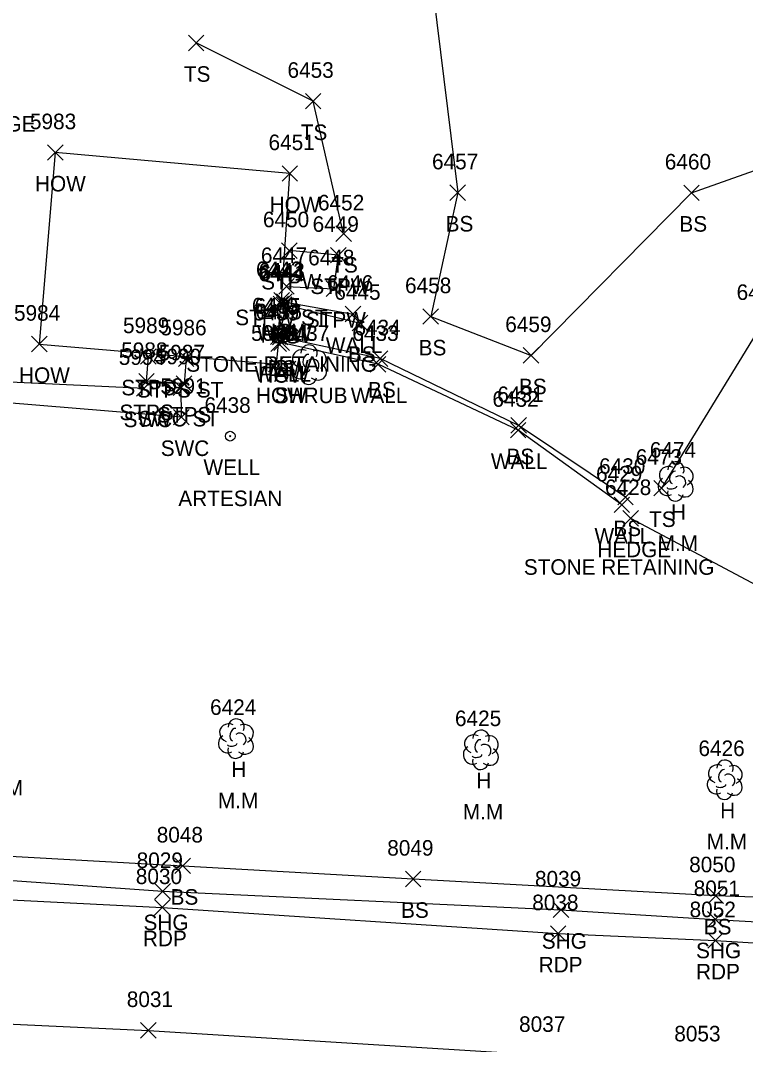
# Model space of a CAD drawing. Extents: x 1588028 to 1589597, y 137576 to 138176.
# Drawn here: x 1588574.1 to 1588667.4, y 137897.5 to 138029.2 of the extents above; entities that cross this region are included whole.
import ezdxf

# ---------------------------------------------------------------- set-up
doc = ezdxf.new("R2010")
doc.units = 0
for name, color, linetype in [('L_A', 7, 'Continuous'), ('L_C', 7, 'Continuous'), ('L_I', 7, 'Continuous'), ('L_TIC', 7, 'Continuous'), ('LAHR', 7, 'Continuous'), ('LBC', 7, 'Continuous'), ('LBF', 7, 'Continuous'), ('LELB', 7, 'Continuous'), ('LSH', 7, 'Continuous'), ('LTD', 7, 'Continuous'), ('LW', 7, 'Continuous'), ('P_A', 7, 'Continuous'), ('P_I', 7, 'Continuous'), ('P_TIC', 7, 'Continuous'), ('PET', 7, 'Continuous'), ('PRC', 7, 'Continuous'), ('PSU', 7, 'Continuous'), ('R_A', 7, 'Continuous'), ('R_I', 7, 'Continuous'), ('R_TIC', 7, 'Continuous'), ('RSW', 7, 'Continuous'), ('U_A', 7, 'Continuous'), ('U_C', 7, 'Continuous'), ('U_I', 7, 'Continuous'), ('UWW', 7, 'Continuous')]:
    doc.layers.add(name, color=color, linetype=linetype)

msp = doc.modelspace()

# ---------------------------------------------------------------- linework, layer by layer
at = {"layer": 'L_TIC'}
for points in [[(1588595.7, 138025.3), (1588597.7, 138027.3)], [(1588597.7, 138025.3), (1588595.7, 138027.3)], [(1588610.74, 138017.81), (1588612.74, 138019.81)], [(1588612.74, 138017.81), (1588610.74, 138019.81)], [(1588577.57, 138011.2), (1588579.57, 138013.2)], [(1588579.57, 138011.2), (1588577.57, 138013.2)], [(1588607.74, 138008.51), (1588609.74, 138010.51)], [(1588609.74, 138008.51), (1588607.74, 138010.51)], [(1588629.34, 138006.04), (1588631.34, 138008.04)], [(1588631.34, 138006.04), (1588629.34, 138008.04)], [(1588659.41, 138006.02), (1588661.41, 138008.02)], [(1588661.41, 138006.02), (1588659.41, 138008.02)], [(1588614.66, 138000.76), (1588616.66, 138002.76)], [(1588616.66, 138000.76), (1588614.66, 138002.76)], [(1588607.67, 137998.59), (1588609.67, 138000.59)], [(1588609.67, 137998.59), (1588607.67, 138000.59)], [(1588613.98, 137998), (1588615.98, 138000)], [(1588615.98, 137998), (1588613.98, 138000)], [(1588607.32, 137993.99), (1588609.32, 137995.99)], [(1588609.32, 137993.99), (1588607.32, 137995.99)], [(1588613.41, 137993.69), (1588615.41, 137995.69)], [(1588615.41, 137993.69), (1588613.41, 137995.69)], [(1588606.58, 137991.73), (1588608.58, 137993.73)], [(1588608.58, 137991.73), (1588606.58, 137993.73)], [(1588606.69, 137992.18), (1588608.69, 137994.18)], [(1588608.69, 137992.18), (1588606.69, 137994.18)], [(1588607, 137991.64), (1588609, 137993.64)], [(1588609, 137991.64), (1588607, 137993.64)], [(1588607.03, 137992.01), (1588609.03, 137994.01)], [(1588609.03, 137992.01), (1588607.03, 137994.01)], [(1588615.88, 137990.42), (1588617.88, 137992.42)], [(1588617.88, 137990.42), (1588615.88, 137992.42)], [(1588616.77, 137989.27), (1588618.77, 137991.27)], [(1588618.77, 137989.27), (1588616.77, 137991.27)], [(1588625.86, 137990.11), (1588627.86, 137992.11)], [(1588627.86, 137990.11), (1588625.86, 137992.11)], [(1588606.25, 137987.52), (1588608.25, 137989.52)], [(1588608.25, 137987.52), (1588606.25, 137989.52)], [(1588575.52, 137986.57), (1588577.52, 137988.57)], [(1588577.52, 137986.57), (1588575.52, 137988.57)], [(1588606.3, 137986.6), (1588608.3, 137988.6)], [(1588608.3, 137986.6), (1588606.3, 137988.6)], [(1588606.5, 137987.47), (1588608.5, 137989.47)], [(1588608.5, 137987.47), (1588606.5, 137989.47)], [(1588606.7, 137986.74), (1588608.7, 137988.74)], [(1588608.7, 137986.74), (1588606.7, 137988.74)], [(1588589.55, 137984.97), (1588591.55, 137986.97)], [(1588591.55, 137984.97), (1588589.55, 137986.97)], [(1588638.77, 137985.11), (1588640.77, 137987.11)], [(1588640.77, 137985.11), (1588638.77, 137987.11)], [(1588594.4, 137984.69), (1588596.4, 137986.69)], [(1588596.4, 137984.69), (1588594.4, 137986.69)], [(1588606.01, 137983.98), (1588608.01, 137985.98)], [(1588608.01, 137983.98), (1588606.01, 137985.98)], [(1588619.09, 137983.97), (1588621.09, 137985.97)], [(1588621.09, 137983.97), (1588619.09, 137985.97)], [(1588619.36, 137984.69), (1588621.36, 137986.69)], [(1588621.36, 137984.69), (1588619.36, 137986.69)], [(1588589.31, 137981.78), (1588591.31, 137983.78)], [(1588591.31, 137981.78), (1588589.31, 137983.78)], [(1588594.13, 137981.47), (1588596.13, 137983.47)], [(1588596.13, 137981.47), (1588594.13, 137983.47)], [(1588637.17, 137976.11), (1588639.17, 137978.11)], [(1588639.17, 137976.11), (1588637.17, 137978.11)], [(1588637.11, 137975.5), (1588639.11, 137977.5)], [(1588639.11, 137975.5), (1588637.11, 137977.5)], [(1588655.54, 137968.04), (1588657.54, 137970.04)], [(1588657.54, 137968.04), (1588655.54, 137970.04)], [(1588650.92, 137966.87), (1588652.92, 137968.87)], [(1588652.92, 137966.87), (1588650.92, 137968.87)], [(1588650.44, 137965.89), (1588652.44, 137967.89)], [(1588652.44, 137965.89), (1588650.44, 137967.89)], [(1588651.59, 137964.15), (1588653.59, 137966.15)], [(1588653.59, 137964.15), (1588651.59, 137966.15)], [(1588593.96, 137919.46), (1588595.96, 137921.46)], [(1588595.96, 137919.46), (1588593.96, 137921.46)], [(1588623.61, 137917.77), (1588625.61, 137919.77)], [(1588625.61, 137917.77), (1588623.61, 137919.77)], [(1588662.54, 137915.63), (1588664.54, 137917.63)], [(1588664.54, 137915.63), (1588662.54, 137917.63)]]:
    msp.add_lwpolyline(points, dxfattribs=at)
at = {"layer": 'LAHR'}
msp.add_lwpolyline([(1588676.23, 137952.57), (1588652.59, 137965.15)], dxfattribs=at)
at = {"layer": 'LBC'}
for points in [[(1588578.57, 138012.2), (1588576.52, 137987.57), (1588607.01, 137984.98), (1588607.3, 137987.6), (1588607.25, 137988.52), (1588607.58, 137992.73), (1588607.69, 137993.18), (1588608.74, 138009.51)], [(1588608.74, 138009.51), (1588578.57, 138012.2)]]:
    msp.add_lwpolyline(points, dxfattribs=at)
at = {"layer": 'LBF'}
for points in [[(1588608.32, 137994.99), (1588614.41, 137994.69), (1588614.98, 137999), (1588608.67, 137999.59)], [(1588595.4, 137985.69), (1588595.13, 137982.47), (1588590.31, 137982.78), (1588590.55, 137985.97)]]:
    msp.add_lwpolyline(points, dxfattribs=at)
at = {"layer": 'LELB'}
for points in [[(1588591.54, 138046.29), (1588626.32, 138039.75), (1588630.34, 138007.04), (1588626.86, 137991.11), (1588639.77, 137986.11), (1588660.41, 138007.02), (1588678.67, 138013.51), (1588710.59, 137997.46), (1588735.69, 137986.71)], [(1588615.66, 138001.76), (1588611.74, 138018.81), (1588596.7, 138026.3)], [(1588729.4, 137978.46), (1588684.34, 138002.79), (1588669.52, 137990.24), (1588656.54, 137969.04)], [(1588608, 137992.64), (1588617.77, 137990.27)], [(1588651.92, 137967.87), (1588638.17, 137977.11), (1588620.36, 137985.69), (1588607.5, 137988.47)], [(1588551.14, 137930.49), (1588555.16, 137922.7), (1588594.96, 137920.46), (1588624.61, 137918.77), (1588663.54, 137916.63), (1588704.8, 137915.23), (1588747.54, 137910.9), (1588783.34, 137911.62)]]:
    msp.add_lwpolyline(points, dxfattribs=at)
at = {"layer": 'LSH'}
msp.add_line((1588611.17, 137984.97), (1588611.17, 137984.97), dxfattribs=at)
msp.add_line((1588611.17, 137984.97), (1588611.17, 137984.97), dxfattribs=at)
msp.add_arc((1588611.22, 137986.41), 1.05, 335.5272, 180.9563, dxfattribs=at)
for centre, major_axis, ratio, start_param, end_param in [((1588610.38, 137985.64), (1.21, -0.51), 0.895232, 1.570796, 4.712389), ((1588612.21, 137985.56), (-1.14, -0.48), 0.949671, 1.570796, 4.712389), ((1588610.96, 137985.43), (-0.208, -0.792), 0.645439, 3.141593, 6.283185), ((1588611.67, 137984.81), (-0.5, 0.667), 0.989748, 3.141593, 6.283185), ((1588610.09, 137984.27), (0.58, -1.04), 0.959034, 3.141593, 6.283185), ((1588610.71, 137984.22), (-0.625, -0.083), 0.423636, 0, 3.141593), ((1588612.17, 137984.14), (-1.09, 0.79), 0.841452, 1.570796, 4.712389), ((1588611.17, 137983.47), (0.26, 1.06), 0.942809, 1.570796, 4.712389)]:
    msp.add_ellipse(centre, major_axis=major_axis, ratio=ratio, start_param=start_param, end_param=end_param, dxfattribs=at)
at = {"layer": 'LTD'}
for p, q in [((1588658.35, 137969.96), (1588658.35, 137969.96)), ((1588658.35, 137969.96), (1588658.35, 137969.96)), ((1588601.79, 137936.87), (1588601.79, 137936.87)), ((1588601.79, 137936.87), (1588601.79, 137936.87)), ((1588633.29, 137935.43), (1588633.29, 137935.43)), ((1588633.29, 137935.43), (1588633.29, 137935.43)), ((1588664.66, 137931.58), (1588664.66, 137931.58)), ((1588664.66, 137931.58), (1588664.66, 137931.58))]:
    msp.add_line(p, q, dxfattribs=at)
for centre in [(1588658.4, 137971.39), (1588601.84, 137938.3), (1588633.34, 137936.87), (1588664.71, 137933.02)]:
    msp.add_arc(centre, 1.05, 335.5272, 180.9563, dxfattribs=at)
for centre, major_axis, ratio, start_param, end_param in [((1588657.56, 137970.62), (1.21, -0.51), 0.895232, 1.570796, 4.712389), ((1588658.14, 137970.41), (-0.208, -0.792), 0.645439, 3.141593, 6.283185), ((1588659.39, 137970.54), (-1.14, -0.48), 0.949671, 1.570796, 4.712389), ((1588657.27, 137969.25), (0.58, -1.04), 0.959034, 3.141593, 6.283185), ((1588658.85, 137969.79), (-0.5, 0.667), 0.989748, 3.141593, 6.283185), ((1588659.35, 137969.12), (-1.09, 0.79), 0.841452, 1.570796, 4.712389), ((1588658.35, 137968.46), (0.26, 1.06), 0.942809, 1.570796, 4.712389), ((1588657.89, 137969.21), (-0.625, -0.083), 0.423636, 0, 3.141593), ((1588601, 137937.53), (1.21, -0.51), 0.895232, 1.570796, 4.712389), ((1588601.58, 137937.32), (-0.208, -0.792), 0.645439, 3.141593, 6.283185), ((1588602.83, 137937.45), (-1.14, -0.48), 0.949671, 1.570796, 4.712389), ((1588600.71, 137936.16), (0.58, -1.04), 0.959034, 3.141593, 6.283185), ((1588602.29, 137936.7), (-0.5, 0.667), 0.989748, 3.141593, 6.283185), ((1588602.79, 137936.03), (-1.09, 0.79), 0.841452, 1.570796, 4.712389), ((1588632.5, 137936.1), (1.21, -0.51), 0.895232, 1.570796, 4.712389), ((1588634.33, 137936.01), (-1.14, -0.48), 0.949671, 1.570796, 4.712389), ((1588601.79, 137935.37), (0.26, 1.06), 0.942809, 1.570796, 4.712389), ((1588601.33, 137936.12), (-0.625, -0.083), 0.423636, 0, 3.141593), ((1588632.21, 137934.72), (0.58, -1.04), 0.959034, 3.141593, 6.283185), ((1588633.08, 137935.89), (-0.208, -0.792), 0.645439, 3.141593, 6.283185), ((1588633.79, 137935.26), (-0.5, 0.667), 0.989748, 3.141593, 6.283185), ((1588634.29, 137934.6), (-1.09, 0.79), 0.841452, 1.570796, 4.712389), ((1588633.29, 137933.93), (0.26, 1.06), 0.942809, 1.570796, 4.712389), ((1588632.83, 137934.68), (-0.625, -0.083), 0.423636, 0, 3.141593), ((1588663.87, 137932.25), (1.21, -0.51), 0.895232, 1.570796, 4.712389), ((1588664.45, 137932.04), (-0.208, -0.792), 0.645439, 3.141593, 6.283185), ((1588665.7, 137932.17), (-1.14, -0.48), 0.949671, 1.570796, 4.712389), ((1588663.58, 137930.88), (0.58, -1.04), 0.959034, 3.141593, 6.283185), ((1588665.16, 137931.42), (-0.5, 0.667), 0.989748, 3.141593, 6.283185), ((1588665.66, 137930.75), (-1.09, 0.79), 0.841452, 1.570796, 4.712389), ((1588664.66, 137930.08), (0.26, 1.06), 0.942809, 1.570796, 4.712389), ((1588664.2, 137930.83), (-0.625, -0.083), 0.423636, 0, 3.141593)]:
    msp.add_ellipse(centre, major_axis=major_axis, ratio=ratio, start_param=start_param, end_param=end_param, dxfattribs=at)
at = {"layer": 'LW'}
for points in [[(1588608.03, 137993.01), (1588616.88, 137991.42)], [(1588651.44, 137966.89), (1588638.11, 137976.5), (1588620.09, 137984.97), (1588607.7, 137987.74)]]:
    msp.add_lwpolyline(points, dxfattribs=at)
at = {"layer": 'P_TIC'}
for points in [[(1588591.38, 137916.18), (1588593.38, 137918.18)], [(1588593.38, 137916.18), (1588591.38, 137918.18)], [(1588591.35, 137914.11), (1588593.35, 137916.11)], [(1588593.35, 137914.11), (1588591.35, 137916.11)], [(1588642.62, 137913.8), (1588644.62, 137915.8)], [(1588644.62, 137913.8), (1588642.62, 137915.8)], [(1588662.46, 137912.57), (1588664.46, 137914.57)], [(1588664.46, 137912.57), (1588662.46, 137914.57)], [(1588642.26, 137910.75), (1588644.26, 137912.75)], [(1588644.26, 137910.75), (1588642.26, 137912.75)], [(1588662.5, 137909.85), (1588664.5, 137911.85)], [(1588664.5, 137909.85), (1588662.5, 137911.85)], [(1588589.55, 137898.3), (1588591.55, 137900.3)], [(1588591.55, 137898.3), (1588589.55, 137900.3)]]:
    msp.add_lwpolyline(points, dxfattribs=at)
at = {"layer": 'PET'}
msp.add_lwpolyline([(1588422.16, 137923.17), (1588469.2, 137920.73), (1588503.28, 137919.24), (1588517.55, 137918.56), (1588549.94, 137917.25), (1588592.35, 137915.11), (1588643.26, 137911.75), (1588663.5, 137910.85), (1588704.32, 137908.35), (1588747.19, 137904.38), (1588787.69, 137899.08), (1588825.32, 137893.63), (1588865.15, 137887.82), (1588905.82, 137880.77), (1588917.24, 137863.85), (1588927.99, 137847.51)], dxfattribs=at)
at = {"layer": 'PRC'}
msp.add_lwpolyline([(1588420.99, 137907.2), (1588467.18, 137904.92), (1588507.29, 137903.21), (1588549.37, 137901.19), (1588590.55, 137899.3), (1588641.57, 137896.1), (1588661.53, 137894.88), (1588702.39, 137891.26), (1588744.44, 137887.15), (1588784.4, 137882.3), (1588823.71, 137877.3), (1588862.06, 137871.74), (1588917.24, 137863.85)], dxfattribs=at)
at = {"layer": 'PSU'}
msp.add_lwpolyline([(1588548.35, 137920.32), (1588592.38, 137917.18), (1588643.62, 137914.8), (1588663.46, 137913.57), (1588704.41, 137911.28), (1588747.22, 137907.04), (1588788.55, 137903.91), (1588803.43, 137901.36)], dxfattribs=at)
at = {"layer": 'R_TIC'}
for points in [[(1588593.74, 137980.97), (1588595.74, 137982.97)], [(1588595.74, 137980.97), (1588593.74, 137982.97)], [(1588589, 137980.88), (1588591, 137982.88)], [(1588591, 137980.88), (1588589, 137982.88)], [(1588593.78, 137977.17), (1588595.78, 137979.17)], [(1588595.78, 137977.17), (1588593.78, 137979.17)]]:
    msp.add_lwpolyline(points, dxfattribs=at)
at = {"layer": 'RSW'}
msp.add_lwpolyline([(1588594.74, 137981.97), (1588594.78, 137978.17), (1588567.2, 137980.42), (1588567.29, 137982.95), (1588590, 137981.88)], dxfattribs=at)
at = {"layer": 'UWW'}
for radius in [0.625, 0.0833]:
    msp.add_circle((1588601.07, 137975.72), radius, dxfattribs=at)

# ---------------------------------------------------------------- texts
at = {"layer": 'L_A'}
for s, p in [('TS', (1588595.11, 138021.3)), ('GARAGE', (1588564.59, 138014.89)), ('TS', (1588610.15, 138013.81)), ('HOW', (1588575.96, 138007.2)), ('HOW', (1588606.13, 138004.51)), ('BS', (1588628.78, 138002.04)), ('BS', (1588658.85, 138002.02)), ('TS', (1588614.07, 137996.76)), ('STPW', (1588605.06, 137994.59)), ('STPW', (1588611.38, 137994)), ('STPW ST', (1588601.72, 137989.99)), ('STPW', (1588610.8, 137989.69)), ('WALL', (1588604.51, 137988.01)), ('HOW', (1588604.97, 137987.73)), ('HOW', (1588605.08, 137988.18)), ('BS', (1588606.44, 137987.64)), ('WALL', (1588613.37, 137986.42)), ('BS', (1588616.21, 137985.27)), ('BS', (1588625.31, 137986.11)), ('HOW', (1588604.64, 137983.52)), ('HOW', (1588573.91, 137982.57)), ('WALL', (1588604.19, 137982.74)), ('HOW', (1588604.69, 137982.6)), ('BS', (1588605.94, 137983.47)), ('STPS', (1588587.07, 137980.97)), ('BS', (1588638.21, 137981.11)), ('STPS ST', (1588589.05, 137980.69)), ('HOW', (1588604.39, 137979.98)), ('SHRUB', (1588606.8, 137979.97)), ('WALL', (1588616.58, 137979.97)), ('BS', (1588618.8, 137980.69)), ('STPS', (1588586.83, 137977.78)), ('STPS', (1588591.65, 137977.47)), ('BS', (1588636.61, 137972.11)), ('WALL', (1588634.6, 137971.5)), ('TS', (1588654.95, 137964.04)), ('H', (1588657.78, 137964.96)), ('BS', (1588650.36, 137962.87)), ('WALL', (1588647.93, 137961.89)), ('HEDGE', (1588648.29, 137960.15)), ('H', (1588601.22, 137931.87)), ('H', (1588632.72, 137930.43)), ('H', (1588664.09, 137926.58)), ('BS', (1588593.4, 137915.46)), ('BS', (1588623.05, 137913.77)), ('BS', (1588661.98, 137911.63))]:
    msp.add_text(s, height=2, dxfattribs=at).set_placement(p)
at = {"layer": 'L_C'}
for s, p in [('STONE RETAINING', (1588595.42, 137984.01)), ('M.M', (1588656.05, 137960.96)), ('STONE RETAINING', (1588638.84, 137957.89)), ('M.M', (1588569.24, 137929.51)), ('M.M', (1588599.49, 137927.87)), ('M.M', (1588630.99, 137926.43)), ('M.M', (1588662.36, 137922.58))]:
    msp.add_text(s, height=2, dxfattribs=at).set_placement(p)
at = {"layer": 'L_I'}
for s, p in [('6453', (1588608.44, 138021.81)), ('5983', (1588575.31, 138015.2)), ('6451', (1588606, 138012.51)), ('6457', (1588627.03, 138010.04)), ('6460', (1588656.97, 138010.02)), ('6452', (1588612.36, 138004.76)), ('6450', (1588605.28, 138002.59)), ('6449', (1588611.67, 138002)), ('6447', (1588605.02, 137997.99)), ('6448', (1588611.1, 137997.69)), ('6442', (1588604.39, 137996.18)), ('6444', (1588604.69, 137995.64)), ('6443', (1588604.72, 137996.01)), ('6441', (1588604.84, 137995.73)), ('6446', (1588613.52, 137994.42)), ('6458', (1588623.56, 137994.11)), ('6445', (1588614.46, 137993.27)), ('6472', (1588666.21, 137993.24)), ('6440', (1588603.86, 137991.52)), ('6435', (1588604.2, 137991.47)), ('5984', (1588573.26, 137990.57)), ('6439', (1588603.99, 137990.6)), ('6436', (1588604.34, 137990.74)), ('5989', (1588587.28, 137988.97)), ('6459', (1588636.45, 137989.11)), ('5986', (1588592.09, 137988.69)), ('5985', (1588603.75, 137987.98)), ('6437', (1588607.86, 137987.97)), ('6433', (1588616.78, 137987.97)), ('6434', (1588617.05, 137988.69)), ('5988', (1588587.05, 137985.78)), ('5987', (1588591.87, 137985.47)), ('6431', (1588635.43, 137980.11)), ('6432', (1588634.8, 137979.5)), ('6473', (1588653.23, 137972.04)), ('6474', (1588655.04, 137972.96)), ('6430', (1588648.52, 137970.87)), ('6429', (1588648.13, 137969.89)), ('6428', (1588649.28, 137968.15)), ('6424', (1588598.48, 137939.87)), ('6425', (1588629.98, 137938.43)), ('6426', (1588661.3, 137934.58)), ('8048', (1588591.62, 137923.46)), ('8049', (1588621.27, 137921.77)), ('8050', (1588660.11, 137919.63))]:
    msp.add_text(s, height=2, dxfattribs=at).set_placement(p)
at = {"layer": 'P_A'}
for s, p in [('SHG', (1588589.92, 137912.18)), ('RDP', (1588589.84, 137910.11)), ('SHG', (1588641.15, 137909.8)), ('SHG', (1588660.99, 137908.57)), ('RDP', (1588640.75, 137906.75)), ('RDP', (1588660.99, 137905.85))]:
    msp.add_text(s, height=2, dxfattribs=at).set_placement(p)
at = {"layer": 'P_I'}
for s, p in [('8029', (1588589.04, 137920.18)), ('8030', (1588588.93, 137918.11)), ('8039', (1588640.27, 137917.8)), ('8051', (1588660.69, 137916.57)), ('8038', (1588639.92, 137914.75)), ('8052', (1588660.16, 137913.85)), ('8031', (1588587.77, 137902.3)), ('8037', (1588638.23, 137899.1)), ('8053', (1588658.19, 137897.88))]:
    msp.add_text(s, height=2, dxfattribs=at).set_placement(p)
at = {"layer": 'R_A'}
for s, p in [('SWC ST', (1588589.24, 137976.97)), ('SWC', (1588587.36, 137976.88)), ('SWC', (1588592.14, 137973.17))]:
    msp.add_text(s, height=2, dxfattribs=at).set_placement(p)
at = {"layer": 'R_I'}
for s, p in [('5994', (1588586.74, 137984.88)), ('5990', (1588591.39, 137984.97)), ('5991', (1588592.09, 137981.17))]:
    msp.add_text(s, height=2, dxfattribs=at).set_placement(p)
at = {"layer": 'U_A'}
msp.add_text('WELL', height=2, dxfattribs=at).set_placement((1588597.64, 137970.72))
at = {"layer": 'U_C'}
msp.add_text('ARTESIAN', height=2, dxfattribs=at).set_placement((1588594.4, 137966.72))
at = {"layer": 'U_I'}
msp.add_text('6438', height=2, dxfattribs=at).set_placement((1588597.76, 137978.72))

doc.saveas('drawing.dxf')
